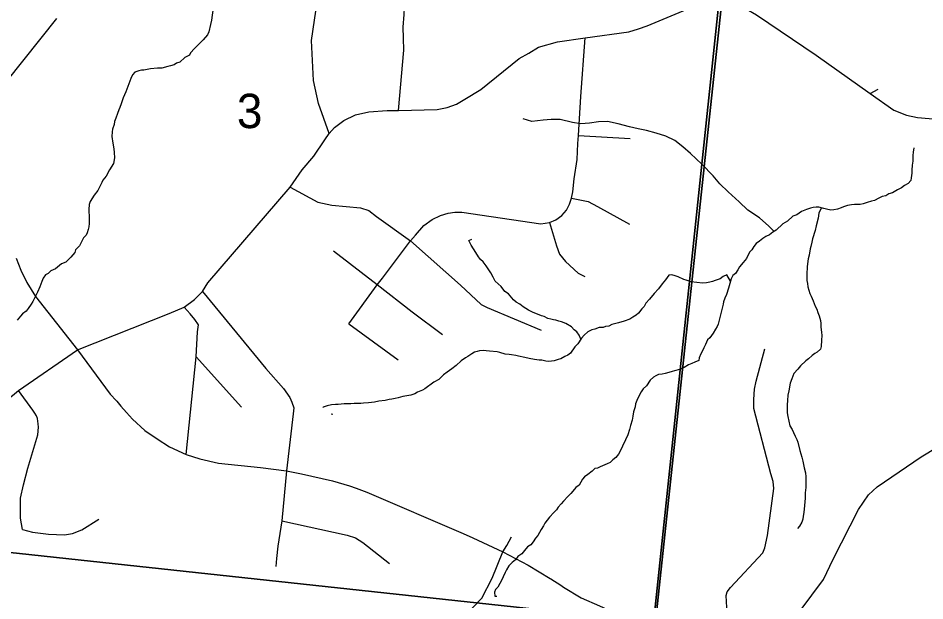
# Model space of a CAD drawing. Extents: x 0 to 34, y -2 to 22.
# Drawn here: x 6.671 to 7.777, y 19.604 to 20.315 of the extents above; entities that cross this region are included whole.
import ezdxf

# ---------------------------------------------------------------- set-up
doc = ezdxf.new("R2010")
doc.units = 0
for name, color, linetype in [('GM_X_City_Street', 7, 'Continuous'), ('GM_X_County_Road', 7, 'Continuous'), ('GM_X_Minor_River', 7, 'Continuous'), ('GM_X_Rail_Line', 7, 'Continuous'), ('GM_X_Section', 7, 'Continuous'), ('GM_X_Section_Text', 7, 'Continuous')]:
    doc.layers.add(name, color=color, linetype=linetype)

msp = doc.modelspace()

# ---------------------------------------------------------------- linework, layer by layer
at = {"layer": 'GM_X_City_Street'}
for p, q in [((7.7105, 20.2233), (7.7204, 20.2283)), ((7.3547, 20.172), (7.4177, 20.1684)), ((7.0746, 19.9422), (7.1349, 19.8984)), ((6.8886, 19.902), (6.9439, 19.8404))]:
    msp.add_line(p, q, dxfattribs=at)
for points in [[(7.0508, 20.1742), (7.0376, 20.211), (7.0314, 20.2389), (7.0291, 20.2879), (7.0366, 20.3379), (7.0476, 20.3874), (7.0737, 20.4444), (7.0797, 20.4522), (7.104, 20.4716)], [(7.1352, 20.2025), (7.1417, 20.2761), (7.1413, 20.2907), (7.1411, 20.3042), (7.1422, 20.3193), (7.1427, 20.3277), (7.1447, 20.336), (7.1495, 20.3487), (7.1526, 20.3556), (7.1563, 20.3625), (7.1721, 20.3867)], [(6.6431, 20.1028), (6.6535, 20.1089), (6.6584, 20.1145), (6.6594, 20.1209), (6.6581, 20.1278), (6.6475, 20.1493), (6.6405, 20.1667), (6.6386, 20.1742), (6.6375, 20.1801), (6.6374, 20.1882), (6.6382, 20.1957), (6.641, 20.2095), (6.6458, 20.2193), (6.6512, 20.2278), (6.6577, 20.2386), (6.7186, 20.3145)], [(7.354, 20.1623), (7.3547, 20.172), (7.3578, 20.2196), (7.3628, 20.291)], [(7.0746, 19.9422), (7.1094, 19.9896), (7.1156, 19.998), (7.1499, 20.0434), (7.1561, 20.0502), (7.1661, 20.0623), (7.1762, 20.0693), (7.1866, 20.0743), (7.1957, 20.0773), (7.2039, 20.0782), (7.2123, 20.0785), (7.3088, 20.0642), (7.3195, 20.0658), (7.3271, 20.0689), (7.3344, 20.0743), (7.34, 20.0808), (7.344, 20.0882), (7.3461, 20.0954), (7.3479, 20.1031), (7.3495, 20.119), (7.3533, 20.1426), (7.354, 20.1623)], [(7.0029, 20.1087), (7.0368, 20.0906), (7.054, 20.0868), (7.0887, 20.0836), (7.0989, 20.0805), (7.1084, 20.0732), (7.1499, 20.0434), (7.1931, 20.0052), (7.2109, 19.9895), (7.2362, 19.9659), (7.2432, 19.9621), (7.3091, 19.9345)], [(7.3461, 20.0954), (7.3666, 20.0913), (7.3781, 20.0853), (7.417, 20.0637)], [(7.3195, 20.0658), (7.3278, 20.0374), (7.3318, 20.0271), (7.339, 20.0181), (7.3546, 20.0041), (7.3625, 20.0001)], [(7.1889, 19.9289), (7.1518, 19.9564), (7.1094, 19.9896), (7.0561, 20.0309)], [(6.8963, 19.9817), (6.9734, 19.8877), (6.995, 19.8634), (7.0027, 19.8525), (7.0052, 19.8466), (7.0074, 19.8399), (7.0069, 19.8324), (6.9988, 19.7629), (6.993, 19.7021), (6.9881, 19.6709), (6.9865, 19.6561), (6.9855, 19.6462)], [(6.8763, 19.7827), (6.8886, 19.902), (6.8902, 19.9326), (6.8911, 19.9411), (6.8868, 19.9473), (6.8812, 19.9545), (6.8739, 19.9626)], [(7.6543, 19.4514), (7.5674, 19.5013), (7.5509, 19.5109), (7.5455, 19.5369), (7.5364, 19.5816), (7.5349, 19.6107), (7.5362, 19.6152), (7.5401, 19.6205), (7.5796, 19.6631), (7.582, 19.6691), (7.5854, 19.6839), (7.593, 19.7414), (7.5921, 19.7498), (7.5893, 19.7594), (7.5687, 19.839), (7.5686, 19.85), (7.5697, 19.8625), (7.5714, 19.8723), (7.582, 19.9119)], [(6.6764, 19.6915), (6.674, 19.7053), (6.6743, 19.7296), (6.6777, 19.746), (6.6832, 19.766), (6.6951, 19.807), (6.6961, 19.8162), (6.6957, 19.8201), (6.6953, 19.8236), (6.6947, 19.8266), (6.6935, 19.8301), (6.6916, 19.8334), (6.689, 19.837), (6.6716, 19.8607)], [(6.6764, 19.6915), (6.6888, 19.6881), (6.7085, 19.6858), (6.7277, 19.685), (6.7377, 19.6865), (6.7491, 19.6908), (6.7696, 19.704)], [(6.993, 19.7021), (7.0728, 19.6844), (7.0828, 19.6811), (7.0917, 19.6755), (7.1242, 19.6497)], [(6.9742, 19.4112), (6.998, 19.4336), (7.0249, 19.464), (7.0622, 19.5013), (7.0924, 19.5313), (7.1056, 19.5424), (7.1256, 19.5517), (7.1468, 19.5559), (7.1652, 19.558), (7.1795, 19.562), (7.1948, 19.5714), (7.2114, 19.5834), (7.2252, 19.5956), (7.2369, 19.6078), (7.2495, 19.6321), (7.2627, 19.6641), (7.2673, 19.6719), (7.273, 19.6823)]]:
    msp.add_lwpolyline(points, dxfattribs=at)
at = {"layer": 'GM_X_County_Road'}
for points in [[(7.5387, 20.3321), (7.5465, 20.3306), (7.5593, 20.3265), (7.572, 20.3189), (7.6448, 20.27), (7.7105, 20.2233), (7.7394, 20.2027), (7.7549, 20.1966), (7.7684, 20.194), (7.7824, 20.1925), (7.795, 20.1922), (7.8087, 20.1953), (7.8195, 20.2007), (7.8284, 20.2085), (7.8398, 20.2268), (7.8418, 20.2314)], [(6.6194, 19.8178), (6.6716, 19.8607), (6.7436, 19.9103), (6.8556, 19.9548), (6.8739, 19.9626), (6.8862, 19.9717), (6.8963, 19.9817), (6.9025, 19.9922), (7.0029, 20.1087), (7.0178, 20.1299), (7.0319, 20.1466), (7.0453, 20.1668), (7.0508, 20.1742), (7.0572, 20.1817), (7.0684, 20.19), (7.0828, 20.197), (7.0992, 20.2007), (7.1214, 20.2025), (7.1352, 20.2025), (7.1823, 20.2035), (7.1946, 20.2062), (7.2061, 20.2101), (7.2163, 20.2163), (7.2358, 20.2282), (7.2823, 20.2658), (7.2942, 20.2723), (7.3062, 20.2796), (7.3291, 20.2862), (7.3628, 20.291), (7.4163, 20.2985), (7.4278, 20.302), (7.4385, 20.3056), (7.4922, 20.3281)], [(6.6688, 20.0221), (6.6745, 20.0075), (6.6819, 19.9926), (6.6925, 19.9756), (6.7077, 19.9564), (6.7436, 19.9103), (6.7837, 19.8566), (6.7912, 19.8484), (6.7918, 19.8477)], [(6.7918, 19.8477), (6.7965, 19.8416), (6.8035, 19.834), (6.8109, 19.826), (6.8258, 19.8122), (6.8408, 19.8018), (6.8558, 19.7921), (6.8763, 19.7827), (6.8929, 19.7774), (6.9158, 19.7722), (6.9668, 19.7669), (6.9988, 19.7629), (7.017, 19.7591), (7.0546, 19.7506), (7.0753, 19.7447), (7.0836, 19.7419), (7.0968, 19.737), (7.2141, 19.6865), (7.226, 19.681)], [(7.4347, 19.4382), (7.4921, 19.45), (7.5027, 19.4538), (7.5138, 19.4604), (7.5307, 19.4796), (7.5509, 19.5109), (7.5527, 19.5131), (7.576, 19.5394), (7.6036, 19.5706), (7.625, 19.5923), (7.6537, 19.6303), (7.6656, 19.6552), (7.6964, 19.7157), (7.7085, 19.7337), (7.719, 19.7433), (7.7728, 19.7798), (7.8449, 19.8234), (7.8458, 19.824), (7.8719, 19.8382), (7.8818, 19.8407), (7.8988, 19.84), (8.0067, 19.8298), (8.1129, 19.8197), (8.187, 19.8127)], [(7.226, 19.681), (7.2627, 19.6641), (7.2933, 19.6477), (7.3201, 19.6316), (7.321, 19.6311), (7.3332, 19.6234)], [(7.3332, 19.6234), (7.3367, 19.6212), (7.358, 19.6082), (7.3805, 19.5981), (7.3948, 19.5917), (7.4121, 19.5856), (7.4378, 19.5807), (7.4469, 19.5805), (7.4654, 19.58)]]:
    msp.add_lwpolyline(points, dxfattribs=at)
at = {"layer": 'GM_X_Minor_River'}
for points in [[(6.9093, 20.3274), (6.907, 20.3126), (6.9061, 20.3073), (6.904, 20.2982), (6.9024, 20.2948), (6.8969, 20.2885), (6.8918, 20.2833), (6.8863, 20.2778), (6.8816, 20.2729), (6.8804, 20.2699), (6.8746, 20.267), (6.8684, 20.2615), (6.8645, 20.2601), (6.8614, 20.2579), (6.8572, 20.2569), (6.8538, 20.2562), (6.8465, 20.2541), (6.8412, 20.2539), (6.8328, 20.253), (6.8248, 20.2517), (6.8217, 20.2514), (6.8183, 20.2507), (6.8137, 20.2493), (6.8109, 20.246), (6.8089, 20.2415), (6.8064, 20.2351), (6.8028, 20.2253), (6.7995, 20.2177), (6.797, 20.2106), (6.7954, 20.206), (6.7942, 20.203), (6.7925, 20.1989), (6.7905, 20.1929), (6.7888, 20.1891), (6.7884, 20.1853), (6.7863, 20.1796), (6.7858, 20.1762), (6.7857, 20.1705), (6.7866, 20.1625), (6.7879, 20.1556), (6.7886, 20.151), (6.7888, 20.1445), (6.7874, 20.1377), (6.7827, 20.1302), (6.7787, 20.1223), (6.7744, 20.1175), (6.7735, 20.1145), (6.7683, 20.1047), (6.764, 20.0991), (6.7592, 20.0913), (6.758, 20.0879), (6.7574, 20.0818), (6.7577, 20.0784), (6.758, 20.0742), (6.7579, 20.07), (6.7581, 20.0646), (6.7576, 20.0605), (6.7567, 20.0571)], [(7.5935, 20.055), (7.5871, 20.0613), (7.5756, 20.0715), (7.5614, 20.0809), (7.5506, 20.0911), (7.5372, 20.1032), (7.5272, 20.113), (7.5191, 20.1227), (7.5054, 20.1371), (7.4916, 20.15), (7.482, 20.1582), (7.4723, 20.1656), (7.4614, 20.1712), (7.4497, 20.1749), (7.4376, 20.1779), (7.4274, 20.18), (7.4172, 20.1826), (7.4032, 20.1863), (7.39, 20.1889), (7.3793, 20.1884), (7.3683, 20.1868), (7.3576, 20.1863), (7.3474, 20.1877), (7.3323, 20.1915), (7.3216, 20.1914), (7.3117, 20.1905), (7.298, 20.1889), (7.2875, 20.1922)], [(7.7638, 20.1569), (7.7632, 20.1516), (7.7627, 20.1474), (7.7626, 20.1406), (7.762, 20.1356), (7.7615, 20.1296), (7.7614, 20.1258), (7.7605, 20.1204), (7.76, 20.117), (7.7569, 20.1133), (7.7526, 20.1108), (7.7487, 20.1082), (7.7441, 20.1057), (7.7379, 20.102), (7.7333, 20.1006), (7.7299, 20.0984), (7.7253, 20.0974), (7.721, 20.0953), (7.716, 20.0927), (7.7122, 20.0917), (7.7068, 20.09), (7.7022, 20.0886), (7.6984, 20.0879), (7.695, 20.0876), (7.6915, 20.0877), (7.6877, 20.0874), (7.6828, 20.0864), (7.6781, 20.0847), (7.6751, 20.0836), (7.6708, 20.0822), (7.6663, 20.0812), (7.6628, 20.0809), (7.6575, 20.0822), (7.6541, 20.083), (7.6481, 20.0844), (7.6447, 20.0845), (7.6409, 20.0842), (7.6378, 20.0831), (7.6328, 20.0817), (7.627, 20.0792), (7.6212, 20.0752), (7.6162, 20.0734), (7.6096, 20.0675), (7.6042, 20.0643), (7.596, 20.0565), (7.5917, 20.0539), (7.5879, 20.0506), (7.5832, 20.0488), (7.5798, 20.0463), (7.5755, 20.043), (7.5716, 20.04), (7.5685, 20.0367), (7.5661, 20.0326), (7.5633, 20.0296), (7.5597, 20.0217), (7.5558, 20.0172), (7.5511, 20.0117), (7.549, 20.0079), (7.5463, 20.0034), (7.5432, 20.0012), (7.5411, 19.9971), (7.5378, 19.9857), (7.5353, 19.9778), (7.5333, 19.9737), (7.5316, 19.9692), (7.5312, 19.9661), (7.5286, 19.9548), (7.5277, 19.9514), (7.5252, 19.9419), (7.524, 19.9389), (7.522, 19.9355), (7.5192, 19.9307), (7.5152, 19.9251), (7.5121, 19.9225), (7.5097, 19.9168), (7.5077, 19.9131), (7.5065, 19.9101), (7.5041, 19.9056), (7.502, 19.9007), (7.5016, 19.8976), (7.4966, 19.8955), (7.4931, 19.8937), (7.4889, 19.8923), (7.4838, 19.889), (7.4781, 19.8865), (7.4719, 19.8848), (7.4689, 19.8841), (7.465, 19.883), (7.4604, 19.8816), (7.457, 19.881), (7.4524, 19.8803), (7.4493, 19.8789), (7.4463, 19.8771), (7.4423, 19.8734), (7.4376, 19.8667), (7.4337, 19.863), (7.4313, 19.8592), (7.4285, 19.854), (7.4261, 19.8487), (7.4245, 19.8446), (7.424, 19.8411)], [(7.6511, 20.0839), (7.6479, 20.0771), (7.6473, 20.071), (7.6448, 20.0616), (7.6435, 20.0559), (7.6402, 20.0457), (7.6393, 20.0416), (7.6384, 20.0366), (7.6372, 20.0336), (7.6362, 20.026), (7.635, 20.0215), (7.6336, 20.012), (7.6333, 20.0025), (7.6335, 19.9949), (7.6342, 19.9914), (7.6344, 19.9872), (7.6369, 19.9792), (7.6387, 19.9761), (7.6412, 19.9703), (7.6423, 19.9672), (7.6437, 19.9637), (7.6455, 19.9599), (7.6469, 19.956), (7.6483, 19.9518), (7.65, 19.9461), (7.6503, 19.9426), (7.6506, 19.938), (7.6512, 19.9319), (7.6515, 19.9281), (7.6513, 19.9224), (7.6507, 19.9144), (7.6499, 19.9114), (7.646, 19.9077), (7.6429, 19.9059), (7.6398, 19.9037), (7.6355, 19.8996), (7.632, 19.897), (7.6257, 19.8911), (7.6222, 19.887), (7.6175, 19.8818), (7.615, 19.875), (7.613, 19.8698), (7.6112, 19.8603), (7.6103, 19.855), (7.6098, 19.8485), (7.6092, 19.8436), (7.6095, 19.8386), (7.6094, 19.8337), (7.61, 19.8291), (7.6114, 19.8234), (7.6127, 19.818), (7.6153, 19.8133), (7.6171, 19.8095), (7.6192, 19.8052), (7.621, 19.801), (7.6225, 19.7979), (7.6248, 19.7879), (7.6273, 19.7795), (7.6283, 19.7749), (7.63, 19.7665), (7.6317, 19.7603), (7.632, 19.7554), (7.6322, 19.7523), (7.632, 19.7424), (7.6314, 19.736), (7.6312, 19.7295), (7.6306, 19.7207), (7.6296, 19.712), (7.6288, 19.7075), (7.6283, 19.7041), (7.6274, 19.7003), (7.6242, 19.6954), (7.6218, 19.6926)], [(6.7567, 20.0571), (6.7555, 20.0533), (6.7543, 20.0503), (6.7511, 20.0469), (6.7463, 20.0372), (6.7412, 20.0324), (6.7404, 20.0293), (6.7357, 20.0234), (6.7322, 20.0204), (6.7294, 20.0175), (6.724, 20.0153), (6.7167, 20.0094), (6.7113, 20.0069), (6.7081, 20.0036), (6.7047, 20.0018), (6.7019, 19.998), (6.7003, 19.9939), (6.6978, 19.9875), (6.695, 19.9807), (6.6918, 19.9743), (6.6893, 19.9694), (6.687, 19.9661), (6.6834, 19.9609), (6.681, 19.9575), (6.6764, 19.9546), (6.674, 19.9516), (6.6701, 19.9468)], [(7.3576, 19.9233), (7.3556, 19.9284), (7.3527, 19.9326), (7.3497, 19.935), (7.3464, 19.9385), (7.3393, 19.9425), (7.334, 19.9446), (7.331, 19.9454), (7.3272, 19.9467), (7.3242, 19.9471), (7.3212, 19.948), (7.3174, 19.9489), (7.3129, 19.9513), (7.3095, 19.9521), (7.3027, 19.955), (7.2997, 19.9562), (7.2937, 19.959), (7.2873, 19.963), (7.2832, 19.9662), (7.2787, 19.9686), (7.2754, 19.9714), (7.2695, 19.9788), (7.265, 19.9816), (7.2603, 19.9878), (7.2532, 19.9944), (7.2507, 19.9991), (7.2478, 20.0045), (7.2423, 20.013), (7.2386, 20.0177), (7.2353, 20.0208), (7.2327, 20.024), (7.2294, 20.029), (7.224, 20.0383), (7.2211, 20.0437), (7.2246, 20.0455)], [(7.5403, 19.9943), (7.5356, 20.0018), (7.5313, 20), (7.5278, 19.9971), (7.5217, 19.995), (7.5182, 19.9939), (7.5152, 19.9932), (7.511, 19.9922), (7.506, 19.9916), (7.4924, 19.9935), (7.4863, 19.9956), (7.4833, 19.9964), (7.4762, 19.9997), (7.4728, 20.0009), (7.4686, 20.0018), (7.4648, 20.0015), (7.4609, 19.9959), (7.4569, 19.991), (7.4522, 19.9847), (7.4471, 19.9791), (7.4416, 19.9724), (7.4369, 19.9676), (7.4349, 19.9635), (7.4322, 19.9605), (7.4282, 19.9553), (7.4251, 19.9527), (7.4209, 19.9502), (7.4174, 19.948), (7.4105, 19.9455), (7.4036, 19.9434), (7.3986, 19.942), (7.3955, 19.9413), (7.3917, 19.9395), (7.3878, 19.9389), (7.3848, 19.9378), (7.3802, 19.9376), (7.3748, 19.9358), (7.371, 19.9348), (7.366, 19.9326), (7.3617, 19.9282), (7.3586, 19.9249), (7.3542, 19.9177), (7.3503, 19.914), (7.3451, 19.9066), (7.342, 19.904), (7.3382, 19.9022), (7.3332, 19.8997), (7.3301, 19.8986), (7.3251, 19.8972), (7.322, 19.8966), (7.3186, 19.8963), (7.3148, 19.8968), (7.3099, 19.8977), (7.3069, 19.8977), (7.3012, 19.8987), (7.2948, 19.9), (7.2895, 19.9013), (7.2815, 19.9026), (7.2785, 19.9035), (7.2732, 19.9044), (7.2702, 19.9049), (7.2652, 19.9054), (7.2588, 19.9071), (7.2554, 19.9079), (7.2463, 19.9089), (7.2422, 19.9094), (7.2384, 19.9096), (7.2342, 19.9093), (7.2311, 19.9086), (7.228, 19.9076), (7.2249, 19.9057), (7.2199, 19.9025), (7.2168, 19.9006), (7.2118, 19.897), (7.2055, 19.8914), (7.2005, 19.8874), (7.1947, 19.8834), (7.19, 19.8801), (7.1846, 19.8745), (7.1784, 19.8709), (7.1675, 19.8628), (7.1644, 19.8613), (7.1586, 19.8588), (7.1552, 19.857), (7.1502, 19.8553), (7.1406, 19.8536), (7.1349, 19.8519), (7.1311, 19.8512), (7.1272, 19.8502), (7.1238, 19.8499), (7.1188, 19.8489), (7.1112, 19.848), (7.1058, 19.8466), (7.0986, 19.846), (7.0925, 19.8455), (7.0891, 19.8452), (7.0849, 19.8449), (7.0811, 19.845), (7.0769, 19.8447), (7.0731, 19.8445), (7.0689, 19.8446)], [(7.0689, 19.8446), (7.0655, 19.8443), (7.0617, 19.844), (7.0582, 19.8437), (7.0537, 19.8435), (7.0483, 19.8421), (7.0433, 19.8404), (7.0429, 19.8402)], [(7.053, 19.8324), (7.0552, 19.832)], [(7.424, 19.8411), (7.4219, 19.8347), (7.421, 19.8294), (7.4201, 19.8249), (7.4184, 19.8181), (7.4171, 19.8132), (7.4151, 19.8067), (7.4122, 19.8007), (7.4086, 19.7928), (7.4058, 19.7868), (7.4034, 19.7831), (7.4002, 19.779), (7.3968, 19.7764), (7.3936, 19.7731), (7.3898, 19.7716), (7.3813, 19.7677), (7.3778, 19.7663), (7.3748, 19.7656), (7.3713, 19.7626), (7.3662, 19.7586), (7.3623, 19.7557), (7.3596, 19.7527), (7.3556, 19.7456), (7.3517, 19.7426), (7.3478, 19.7382), (7.3454, 19.7352), (7.3419, 19.7318), (7.3364, 19.7259), (7.3337, 19.7226), (7.3302, 19.7188), (7.3278, 19.7155), (7.3247, 19.7121), (7.3196, 19.7066), (7.3137, 19.6991), (7.312, 19.6957), (7.3093, 19.6912), (7.3073, 19.6879), (7.3053, 19.6841), (7.3025, 19.6808), (7.2997, 19.6763), (7.2966, 19.6726), (7.2927, 19.6704), (7.2888, 19.6659), (7.2856, 19.6618), (7.281, 19.6585), (7.2778, 19.6544), (7.2739, 19.6511), (7.27, 19.647), (7.2669, 19.6422), (7.2652, 19.6388), (7.2628, 19.6335), (7.2612, 19.6301), (7.2564, 19.6211), (7.2537, 19.6181), (7.2524, 19.6151), (7.2527, 19.6102), (7.2551, 19.6102)]]:
    msp.add_lwpolyline(points, dxfattribs=at)
at = {"layer": 'GM_X_Rail_Line'}
for points in [[(7.2924, 18.0527), (7.3254, 18.3889), (7.3765, 18.917), (7.3781, 18.9333), (7.4316, 19.4382), (7.4466, 19.581), (7.5261, 20.3339), (7.5512, 20.5718), (7.5526, 20.5853), (7.5548, 20.6102), (7.5809, 20.9), (2.1, 20.9)], [(8.9, 16.3574), (8.9, 20.9), (7.5809, 20.9), (7.5548, 20.6102), (7.5526, 20.5853), (7.5512, 20.5718), (7.5261, 20.3339), (7.4466, 19.581), (7.4316, 19.4382), (7.3781, 18.9333), (7.3765, 18.917), (7.3254, 18.3889), (7.2924, 18.0527)]]:
    msp.add_lwpolyline(points, dxfattribs=at)
at = {"layer": 'GM_X_Section'}
for points in [[(6.545, 20.6847), (7.556, 20.5828), (7.4489, 19.5784), (6.443, 19.687)], [(8.5471, 20.4749), (8.4442, 19.5041), (7.4489, 19.5784), (7.556, 20.5828)], [(7.4489, 19.5784), (7.3433, 18.5849), (6.3407, 18.6907), (6.443, 19.687)]]:
    msp.add_lwpolyline(points, close=True, dxfattribs=at)

# ---------------------------------------------------------------- texts
at = {"layer": 'GM_X_Section_Text'}
msp.add_text('3', height=0.0419, rotation=0, dxfattribs=at).set_placement((6.9381, 20.1809))

doc.saveas('drawing.dxf')
